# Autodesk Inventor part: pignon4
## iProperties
Author: Administrateur
Shininess: 20.0
PropertySet Name: _Private Model Information
Length Units: 11269
Angle Units: 11283
Time Units: 11279
Mass Units: 11290
Length Display Precision: 3
Angle Display Precision: 2
Compacted: False
Created: 2001-04
Part Number: pignon4
Material: Par défaut
Document SubType Name: Modélisation
Designer: Administrateur
Control State: 0
Master: False
Checked Out: False
PropertySet Name: Design Tracking Control
Density: 0.0
Volumn: 0.0
Area: 0.0
PropertySet Name: Model Information
